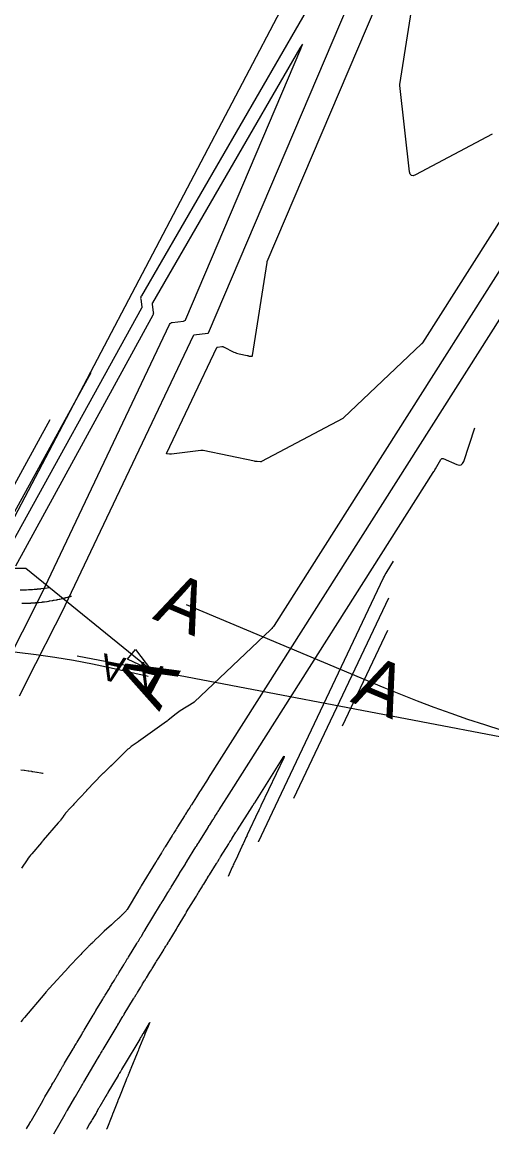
# Model space of a CAD drawing. Extents: x 688474 to 694748, y 765018 to 767373.
# Drawn here: x 688853.2 to 688960.5, y 766872 to 767124.6 of the extents above; entities that cross this region are included whole.
import ezdxf

# ---------------------------------------------------------------- set-up
doc = ezdxf.new("R2010")
doc.units = 0
for name, color, linetype in [('Default', 7, 'Continuous'), ('Prop_Contours_Major', 7, 'Continuous'), ('Prop_Contours_Minor', 7, 'Continuous'), ('R_Horz Alg', 7, 'Continuous')]:
    doc.layers.add(name, color=color, linetype=linetype)

msp = doc.modelspace()

# ---------------------------------------------------------------- linework, layer by layer
at = {"layer": 'Default'}
msp.add_lwpolyline([(689001.05, 766954.08), (688971.09, 766959.79), (688865.78, 766979.87)], dxfattribs=at)
at = {"layer": 'Prop_Contours_Major'}
for points in [[(688929.91, 767147.6), (688880.43, 767062.16), (688880.34, 767061.97), (688880.29, 767061.78), (688880.26, 767061.57), (688880.28, 767061.37), (688880.54, 767059.61), (688880.54, 767059.53), (688880.53, 767059.45), (688880.51, 767059.38), (688880.48, 767059.31), (688849.65, 767003.45)], [(688852.62, 766970.81), (688854.13, 766973.82), (688854.15, 766973.86), (688862.99, 766991.35), (688863, 766991.37), (688863.01, 766991.39), (688863.02, 766991.41), (688863.03, 766991.43), (688892.38, 767053.23), (688892.38, 767053.23), (688892.39, 767053.23), (688895.65, 767053.62), (688895.69, 767053.63), (688895.73, 767053.65), (688895.75, 767053.67), (688895.77, 767053.71), (688934.73, 767145.25)], [(688992.14, 767115.06), (688910.76, 766986.88), (688910.6, 766986.64), (688910.42, 766986.41), (688910.22, 766986.19), (688910.02, 766985.98), (688892.48, 766969.38), (688892.47, 766969.36), (688892.45, 766969.35), (688892.43, 766969.33), (688892.41, 766969.32), (688889.3, 766967.38), (688888.98, 766967.17), (688888.66, 766966.95), (688888.36, 766966.72), (688888.06, 766966.48), (688886.89, 766965.49), (688886.59, 766965.25), (688886.29, 766965.01), (688885.98, 766964.78), (688885.67, 766964.56), (688879.77, 766960.39), (688879.77, 766960.38), (688879.75, 766960.37), (688879.75, 766960.37), (688879.73, 766960.36), (688878.13, 766959.22), (688877.86, 766959.03), (688877.61, 766958.83), (688877.36, 766958.61), (688877.12, 766958.39), (688873.74, 766955.06), (688873.7, 766955.03), (688873.66, 766954.99), (688873.62, 766954.96), (688873.58, 766954.93), (688873.42, 766954.8), (688873.38, 766954.77), (688873.34, 766954.74), (688873.3, 766954.71), (688873.27, 766954.67), (688871.92, 766953.31), (688871.87, 766953.27), (688871.83, 766953.23), (688871.78, 766953.19), (688871.74, 766953.15), (688871.55, 766953), (688871.5, 766952.97), (688871.46, 766952.93), (688871.41, 766952.89), (688871.37, 766952.84), (688868.03, 766949.36), (688868.02, 766949.35), (688868.01, 766949.33), (688867.99, 766949.32), (688867.98, 766949.3), (688867.93, 766949.23), (688867.91, 766949.21), (688867.9, 766949.19), (688867.88, 766949.17), (688867.87, 766949.16), (688865.04, 766946.11), (688864.84, 766945.89), (688864.64, 766945.67), (688864.44, 766945.46), (688864.24, 766945.24), (688863.13, 766944.04), (688863.08, 766943.99), (688863.04, 766943.93), (688862.99, 766943.88), (688862.95, 766943.82), (688862.78, 766943.58), (688862.74, 766943.53), (688862.7, 766943.47), (688862.66, 766943.41), (688862.61, 766943.35), (688861.98, 766942.45), (688861.85, 766942.29), (688861.73, 766942.12), (688861.6, 766941.96), (688861.46, 766941.8), (688858.01, 766937.84), (688857.99, 766937.82), (688857.98, 766937.81), (688857.97, 766937.79), (688857.96, 766937.77), (688857.91, 766937.71), (688857.9, 766937.69), (688857.89, 766937.67), (688857.87, 766937.66), (688857.86, 766937.64), (688857.73, 766937.49), (688857.71, 766937.46), (688857.68, 766937.43), (688857.65, 766937.4), (688857.63, 766937.37), (688855.39, 766934.77), (688855.12, 766934.44), (688854.85, 766934.11), (688854.59, 766933.76), (688854.35, 766933.41), (688853.03, 766931.46)], [(688853.15, 766991.95), (688853.65, 766991.96), (688853.67, 766991.96), (688853.69, 766991.96), (688853.78, 766991.96), (688853.87, 766991.96), (688853.89, 766991.96), (688853.91, 766991.96), (688853.92, 766991.96), (688853.94, 766991.96), (688854.22, 766991.97), (688854.36, 766991.98), (688854.82, 766992), (688854.85, 766992), (688854.88, 766992), (688854.99, 766992), (688855.1, 766992.01), (688855.13, 766992.01), (688855.15, 766992.01), (688855.17, 766992.01), (688855.19, 766992.02), (688855.5, 766992.04), (688855.62, 766992.05), (688855.74, 766992.05), (688856.27, 766992.09), (688856.33, 766992.1), (688856.39, 766992.1), (688856.45, 766992.11), (688856.51, 766992.11), (688856.74, 766992.13), (688856.85, 766992.15), (688856.97, 766992.16), (688857.61, 766992.22), (688857.63, 766992.22), (688857.65, 766992.23), (688857.75, 766992.24), (688857.84, 766992.25), (688857.86, 766992.25), (688857.89, 766992.25), (688857.91, 766992.26), (688857.93, 766992.26), (688858.15, 766992.29), (688858.24, 766992.3), (688858.33, 766992.31), (688858.86, 766992.38), (688858.9, 766992.39), (688858.93, 766992.39), (688858.95, 766992.4), (688859.24, 766992.44), (688859.35, 766992.46), (688859.45, 766992.48), (688860.02, 766992.57), (688860.06, 766992.58), (688860.1, 766992.58), (688860.14, 766992.59), (688860.17, 766992.6), (688860.33, 766992.63), (688860.41, 766992.64), (688860.49, 766992.65), (688860.96, 766992.74), (688860.99, 766992.75), (688861.02, 766992.76), (688861.12, 766992.77), (688861.27, 766992.81), (688861.3, 766992.81), (688861.32, 766992.82), (688861.35, 766992.82), (688861.38, 766992.83), (688861.63, 766992.88), (688861.68, 766992.9), (688861.73, 766992.91), (688861.79, 766992.92), (688861.84, 766992.93), (688862.4, 766993.05), (688862.47, 766993.07), (688862.54, 766993.09), (688862.61, 766993.11), (688862.69, 766993.12), (688862.97, 766993.2), (688863.05, 766993.21), (688863.12, 766993.23), (688863.19, 766993.25), (688863.26, 766993.27), (688863.69, 766993.38), (688863.72, 766993.39), (688863.75, 766993.39), (688863.78, 766993.4), (688863.81, 766993.41), (688863.97, 766993.45), (688864.05, 766993.47), (688864.16, 766993.5), (688864.19, 766993.51), (688864.23, 766993.53), (688864.35, 766993.56), (688864.44, 766993.58)], [(688936.67, 766985.72), (688926.31, 766963.87)], [(688852.92, 766953.95), (688853.68, 766953.84), (688853.75, 766953.83), (688854.61, 766953.71), (688854.64, 766953.7), (688854.67, 766953.7), (688854.7, 766953.69), (688854.74, 766953.69), (688855.33, 766953.6), (688855.38, 766953.59), (688855.43, 766953.58), (688855.63, 766953.55), (688855.66, 766953.55), (688856.52, 766953.41), (688856.55, 766953.41), (688856.59, 766953.4), (688856.62, 766953.4), (688856.65, 766953.39), (688857.45, 766953.26), (688857.52, 766953.25), (688857.58, 766953.24), (688857.84, 766953.2), (688857.87, 766953.2), (688858.03, 766953.17)]]:
    msp.add_lwpolyline(points, dxfattribs=at)
at = {"layer": 'Prop_Contours_Minor'}
for points in [[(688960.55, 767099.05), (688943.08, 767089.77), (688942.54, 767089.58), (688942.13, 767089.63), (688941.86, 767089.94), (688941.71, 767090.49), (688939.45, 767110.19), (688939.44, 767110.24), (688939.44, 767110.29), (688939.44, 767110.33), (688939.45, 767110.38), (688943.17, 767134.12), (688943.23, 767134.44), (688943.31, 767134.76), (688943.41, 767135.08), (688943.53, 767135.39), (688945.06, 767138.97), (688945.35, 767139.67), (688945.65, 767140.36), (688945.95, 767141.06), (688946.26, 767141.76), (688985.58, 767232.35)], [(688986.13, 767116.74), (688944.65, 767051.41), (688944.6, 767051.35), (688944.55, 767051.28), (688944.5, 767051.22), (688944.44, 767051.16), (688926.64, 767034.3), (688926.6, 767034.27), (688926.56, 767034.24), (688926.52, 767034.21), (688926.47, 767034.18), (688907.87, 767024.3), (688907.81, 767024.28), (688907.75, 767024.26), (688907.69, 767024.25), (688907.63, 767024.25), (688906.86, 767024.3), (688906.71, 767024.31), (688906.56, 767024.33), (688906.41, 767024.35), (688906.26, 767024.38), (688894.56, 767026.81), (688894.43, 767026.84), (688894.3, 767026.85), (688894.17, 767026.85), (688894.04, 767026.84), (688887.3, 767025.99), (688887.18, 767025.98), (688887.06, 767025.98), (688886.94, 767025.98), (688886.83, 767025.99), (688886.35, 767026.04), (688886.25, 767026.06), (688886.2, 767026.11), (688886.19, 767026.18), (688886.22, 767026.27), (688897.64, 767050.34), (688897.67, 767050.38), (688897.71, 767050.42), (688897.76, 767050.44), (688897.81, 767050.46), (688898.8, 767050.57), (688898.91, 767050.58), (688899.01, 767050.57), (688899.11, 767050.54), (688899.21, 767050.5), (688901.53, 767049.32), (688901.83, 767049.18), (688902.13, 767049.07), (688902.45, 767048.97), (688902.77, 767048.9), (688904.63, 767048.56), (688904.67, 767048.55), (688904.71, 767048.54), (688904.75, 767048.52), (688904.79, 767048.51), (688904.94, 767048.43), (688904.97, 767048.42), (688905.01, 767048.41), (688905.05, 767048.4), (688905.09, 767048.39), (688905.59, 767048.36), (688905.67, 767048.37), (688905.74, 767048.4), (688905.79, 767048.46), (688905.81, 767048.54), (688909.14, 767069.78), (688909.15, 767069.83), (688909.16, 767069.89), (688909.18, 767069.94), (688909.2, 767069.99), (688940.22, 767142.88)], [(688848.84, 766976.65), (688857.69, 766994.16), (688857.7, 766994.18), (688857.71, 766994.2), (688886.89, 767055.63), (688887, 767055.81), (688887.14, 767055.94), (688887.31, 767056.03), (688887.5, 767056.08), (688890.02, 767056.37), (688890.21, 767056.42), (688890.37, 767056.5), (688890.49, 767056.63), (688890.59, 767056.8), (688916.88, 767118.58), (688917.2, 767119.35), (688917.26, 767119.63), (688917.07, 767119.41), (688916.64, 767118.7), (688882.98, 767060.57), (688882.93, 767060.48), (688882.91, 767060.39), (688882.9, 767060.29), (688882.9, 767060.19), (688883.16, 767058.43), (688883.17, 767058.25), (688883.16, 767058.06), (688883.11, 767057.89), (688883.03, 767057.72), (688851.68, 767000.41)], [(688981.42, 767087.02), (688895.7, 766952.01), (688895.68, 766951.97), (688893.94, 766949.23), (688893.71, 766948.87), (688893.49, 766948.51), (688893.26, 766948.15), (688893.03, 766947.79), (688891.88, 766945.96), (688891.77, 766945.8), (688891.67, 766945.64), (688891.57, 766945.48), (688891.47, 766945.32), (688890.98, 766944.55), (688890.93, 766944.46), (688890.87, 766944.36), (688890.81, 766944.27), (688890.75, 766944.18), (688890.52, 766943.81), (688890.46, 766943.72), (688890.41, 766943.63), (688890.35, 766943.54), (688890.29, 766943.44), (688888.7, 766940.89), (688888.6, 766940.73), (688888.49, 766940.56), (688888.39, 766940.4), (688888.29, 766940.24), (688887.88, 766939.58), (688887.78, 766939.42), (688887.68, 766939.26), (688887.58, 766939.09), (688887.47, 766938.93), (688885.88, 766936.35), (688885.81, 766936.24), (688885.74, 766936.13), (688885.67, 766936.01), (688885.6, 766935.9), (688885.33, 766935.46), (688885.26, 766935.35), (688885.19, 766935.24), (688885.12, 766935.12), (688885.05, 766935.01), (688884.03, 766933.36), (688883.97, 766933.25), (688883.9, 766933.15), (688883.78, 766932.95), (688883.75, 766932.89), (688883.71, 766932.84), (688883.68, 766932.79), (688883.65, 766932.74), (688880.4, 766927.42), (688880.33, 766927.3), (688880.25, 766927.17), (688880.08, 766926.9), (688880.05, 766926.85), (688880.02, 766926.8), (688880, 766926.76), (688879.97, 766926.71), (688879.8, 766926.43), (688879.78, 766926.4), (688877.16, 766922.06), (688877.06, 766921.9), (688876.95, 766921.75), (688876.82, 766921.61), (688876.69, 766921.47), (688875.99, 766920.78), (688875.93, 766920.72), (688875.87, 766920.66), (688875.81, 766920.6), (688875.75, 766920.54), (688875.44, 766920.24), (688875.42, 766920.21), (688875.39, 766920.19), (688875.37, 766920.16), (688875.35, 766920.14), (688875.25, 766920.05), (688875.22, 766920.02), (688875.2, 766920), (688875.17, 766919.98), (688875.15, 766919.95), (688874.23, 766919.12), (688874.07, 766918.97), (688873.91, 766918.82), (688873.75, 766918.68), (688873.58, 766918.53), (688871.93, 766917.06), (688871.67, 766916.83), (688871.43, 766916.6), (688871.18, 766916.36), (688870.94, 766916.13), (688869.76, 766914.94), (688869.63, 766914.81), (688869.5, 766914.69), (688869.38, 766914.56), (688869.25, 766914.44), (688868.72, 766913.96), (688868.59, 766913.84), (688868.46, 766913.71), (688868.34, 766913.59), (688868.21, 766913.46), (688866.85, 766912.05), (688866.59, 766911.78), (688866.34, 766911.52), (688866.08, 766911.25), (688865.82, 766910.98), (688864.36, 766909.46), (688864.31, 766909.42), (688864.27, 766909.37), (688864.23, 766909.32), (688864.18, 766909.28), (688864.01, 766909.09), (688863.96, 766909.05), (688863.92, 766909), (688863.88, 766908.95), (688863.83, 766908.91), (688859.34, 766903.99), (688859.33, 766903.98), (688859.32, 766903.98), (688859.32, 766903.97), (688859.31, 766903.96), (688859.29, 766903.93), (688859.28, 766903.92), (688859.27, 766903.91), (688859.27, 766903.9), (688859.26, 766903.9), (688858.64, 766903.19), (688858.63, 766903.18), (688858.63, 766903.18), (688858.6, 766903.15), (688858.46, 766902.96), (688858.44, 766902.93), (688858.42, 766902.89), (688858.39, 766902.86), (688858.36, 766902.83), (688853.72, 766897.38), (688853.63, 766897.28), (688853.54, 766897.17), (688853.45, 766897.07), (688853.36, 766896.96), (688852.88, 766896.39)], [(688847.99, 767006.65), (688868.96, 767044.65)], [(688846.56, 767010.26), (688859.59, 767033.88)], [(688854.2, 766871.96), (688854.23, 766872), (688854.28, 766872.09), (688854.87, 766873.13), (688854.91, 766873.19), (688854.94, 766873.25), (688854.98, 766873.32), (688855.01, 766873.38), (688855.16, 766873.63), (688855.23, 766873.76), (688855.31, 766873.89), (688857.9, 766878.38), (688857.94, 766878.45), (688857.98, 766878.53), (688858.02, 766878.6), (688858.06, 766878.67), (688858.23, 766878.95), (688858.31, 766879.09), (688858.39, 766879.24), (688859.79, 766881.64), (688859.84, 766881.73), (688859.9, 766881.82), (688859.95, 766881.91), (688860, 766882.01), (688860.21, 766882.37), (688860.27, 766882.46), (688860.32, 766882.55), (688860.37, 766882.64), (688860.42, 766882.73), (688861.56, 766884.67), (688861.67, 766884.86), (688861.78, 766885.05), (688861.89, 766885.24), (688862.01, 766885.43), (688862.45, 766886.19), (688862.57, 766886.38), (688862.68, 766886.57), (688862.79, 766886.76), (688862.9, 766886.95), (688864.85, 766890.25), (688864.88, 766890.3), (688864.91, 766890.36), (688864.94, 766890.41), (688864.97, 766890.46), (688865.12, 766890.72), (688865.19, 766890.82), (688865.22, 766890.88), (688865.5, 766891.35), (688865.56, 766891.45), (688865.61, 766891.55), (688865.67, 766891.64), (688865.73, 766891.74), (688866.8, 766893.53), (688867, 766893.87), (688867.2, 766894.2), (688867.4, 766894.53), (688867.6, 766894.86), (688869.42, 766897.92), (688869.45, 766897.97), (688869.48, 766898.02), (688869.51, 766898.07), (688869.54, 766898.12), (688869.69, 766898.36), (688869.75, 766898.46), (688869.78, 766898.51), (688869.91, 766898.74), (688869.94, 766898.79), (688869.98, 766898.84), (688870.01, 766898.9), (688870.04, 766898.95), (688871.41, 766901.22), (688871.61, 766901.54), (688871.81, 766901.87), (688872, 766902.19), (688872.2, 766902.52), (688873.12, 766904.04), (688873.25, 766904.25), (688873.38, 766904.47), (688873.51, 766904.68), (688873.64, 766904.9), (688874.26, 766905.92), (688874.35, 766906.06), (688874.43, 766906.19), (688874.52, 766906.33), (688874.6, 766906.47), (688874.93, 766907.02), (688875.02, 766907.15), (688875.1, 766907.29), (688875.19, 766907.43), (688875.27, 766907.57), (688876.41, 766909.43), (688876.5, 766909.57), (688876.59, 766909.72), (688876.68, 766909.87), (688876.77, 766910.01), (688877.13, 766910.6), (688877.22, 766910.75), (688877.31, 766910.89), (688877.4, 766911.04), (688877.49, 766911.19), (688879.41, 766914.28), (688879.49, 766914.42), (688879.58, 766914.56), (688879.67, 766914.7), (688879.76, 766914.85), (688880.11, 766915.41), (688880.19, 766915.56), (688880.28, 766915.7), (688880.37, 766915.84), (688880.46, 766915.98), (688881.03, 766916.91), (688881.1, 766917.03), (688881.22, 766917.22), (688881.24, 766917.26), (688881.27, 766917.3), (688881.29, 766917.34), (688881.31, 766917.37), (688884.83, 766923.2), (688884.9, 766923.31), (688884.96, 766923.41), (688885.09, 766923.63), (688885.12, 766923.68), (688885.15, 766923.73), (688885.18, 766923.78), (688885.21, 766923.82), (688885.38, 766924.11), (688885.39, 766924.13), (688886.51, 766925.95), (688886.7, 766926.26), (688886.88, 766926.56), (688887.07, 766926.87), (688887.25, 766927.17), (688889.05, 766930.1), (688889.07, 766930.14), (688889.09, 766930.17), (688889.16, 766930.28), (688889.17, 766930.3), (688890.48, 766932.43), (688890.51, 766932.47), (688890.54, 766932.52), (688890.56, 766932.57), (688890.59, 766932.61), (688890.74, 766932.84), (688890.79, 766932.94), (688890.82, 766932.98), (688892.91, 766936.36), (688892.97, 766936.44), (688893.02, 766936.52), (688893.07, 766936.6), (688893.12, 766936.69), (688893.33, 766937.02), (688893.38, 766937.1), (688893.43, 766937.18), (688893.48, 766937.26), (688893.53, 766937.35), (688895.67, 766940.77), (688895.7, 766940.82), (688895.74, 766940.87), (688895.77, 766940.93), (688895.8, 766940.98), (688895.93, 766941.19), (688896, 766941.29), (688896.06, 766941.4), (688896.75, 766942.49), (688896.88, 766942.69), (688897, 766942.88), (688897.12, 766943.07), (688897.24, 766943.27), (688897.73, 766944.04), (688897.86, 766944.24), (688897.98, 766944.43), (688898.1, 766944.62), (688898.23, 766944.82), (688900.99, 766949.18), (688901.01, 766949.22), (688947.12, 767021.84), (688947.24, 767022.04), (688947.37, 767022.23), (688947.48, 767022.43), (688947.6, 767022.63), (688948.86, 767024.81), (688948.96, 767024.94), (688949.09, 767025.01), (688949.23, 767025.03), (688949.39, 767024.98), (688952.51, 767023.66), (688953.04, 767023.52), (688953.47, 767023.59), (688953.81, 767023.87), (688954.06, 767024.36), (688956.63, 767032.05)], [(688907.18, 766937.5), (688907.22, 766937.58), (688907.25, 766937.64), (688910.36, 766944.26), (688910.38, 766944.3), (688935.76, 766997.77), (688935.94, 766998.14), (688936.13, 766998.5), (688936.33, 766998.85), (688936.55, 766999.2), (688938.04, 767001.55)], [(688859.39, 766995.51), (688858.45, 766995.36), (688858.42, 766995.35), (688858.38, 766995.35), (688858.37, 766995.34), (688858.15, 766995.31), (688858.05, 766995.3), (688857.5, 766995.23), (688857.47, 766995.23), (688857.45, 766995.22), (688857.36, 766995.21), (688857.27, 766995.2), (688857.26, 766995.2), (688857.24, 766995.2), (688857.22, 766995.2), (688857.21, 766995.2), (688856.84, 766995.16), (688856.77, 766995.15), (688856.71, 766995.15), (688856.64, 766995.14), (688856.57, 766995.13), (688856.25, 766995.1), (688856.17, 766995.09), (688856.09, 766995.09), (688856.02, 766995.08), (688855.94, 766995.07), (688855.56, 766995.05), (688855.5, 766995.04), (688855.44, 766995.04), (688855.38, 766995.04), (688855.32, 766995.03), (688854.99, 766995.01), (688854.97, 766995.01), (688854.95, 766995.01), (688854.93, 766995.01), (688854.9, 766995), (688854.77, 766995), (688854.7, 766994.99), (688854.67, 766994.99), (688854.65, 766994.99), (688854.17, 766994.97), (688854.1, 766994.97), (688854.02, 766994.97), (688853.84, 766994.96), (688853.82, 766994.96), (688853.8, 766994.96), (688853.78, 766994.96), (688853.76, 766994.96), (688853.64, 766994.96), (688853.59, 766994.96), (688853.57, 766994.96), (688853.35, 766994.95), (688853.28, 766994.95), (688853.2, 766994.95), (688852.72, 766994.95)], [(688936.89, 766993.16), (688915.18, 766947.42)], [(688860.45, 766870.86), (688863.02, 766875.31), (688863.1, 766875.46), (688863.19, 766875.6), (688863.36, 766875.9), (688863.4, 766875.98), (688863.44, 766876.05), (688863.49, 766876.12), (688863.53, 766876.2), (688865.24, 766879.13), (688865.28, 766879.21), (688865.34, 766879.31), (688865.37, 766879.35), (688865.38, 766879.37), (688866.84, 766881.88), (688866.97, 766882.1), (688867.22, 766882.53), (688867.24, 766882.56), (688867.28, 766882.62), (688870.33, 766887.8), (688870.36, 766887.84), (688870.44, 766887.98), (688870.92, 766888.79), (688870.99, 766888.9), (688871.05, 766889.01), (688871.12, 766889.12), (688871.18, 766889.23), (688871.44, 766889.67), (688871.51, 766889.78), (688871.58, 766889.89), (688871.64, 766890), (688871.71, 766890.11), (688874.88, 766895.41), (688874.9, 766895.46), (688874.93, 766895.5), (688875.02, 766895.65), (688875.05, 766895.7), (688875.3, 766896.12), (688875.35, 766896.2), (688875.4, 766896.28), (688875.45, 766896.36), (688875.49, 766896.44), (688876.07, 766897.39), (688876.19, 766897.58), (688876.3, 766897.76), (688876.41, 766897.95), (688876.52, 766898.13), (688878.64, 766901.63), (688878.72, 766901.75), (688878.79, 766901.88), (688878.86, 766902), (688878.94, 766902.12), (688879.24, 766902.61), (688879.31, 766902.73), (688879.38, 766902.85), (688879.46, 766902.97), (688879.53, 766903.1), (688880.29, 766904.33), (688880.4, 766904.51), (688880.51, 766904.69), (688880.61, 766904.87), (688880.72, 766905.04), (688881.16, 766905.75), (688881.27, 766905.93), (688881.38, 766906.11), (688881.49, 766906.29), (688881.6, 766906.46), (688882.37, 766907.73), (688882.54, 766908), (688882.71, 766908.27), (688882.87, 766908.54), (688883.04, 766908.81), (688883.73, 766909.93), (688883.9, 766910.21), (688884.07, 766910.48), (688884.25, 766910.76), (688884.42, 766911.03), (688885.54, 766912.85), (688885.6, 766912.95), (688885.67, 766913.06), (688885.73, 766913.16), (688885.79, 766913.26), (688886.05, 766913.68), (688886.11, 766913.78), (688886.17, 766913.87), (688886.23, 766913.97), (688886.29, 766914.07), (688886.53, 766914.45), (688886.59, 766914.55), (688886.65, 766914.65), (688886.71, 766914.75), (688886.77, 766914.84), (688888.42, 766917.58), (688888.63, 766917.93), (688888.84, 766918.27), (688889.05, 766918.62), (688889.26, 766918.97), (688890.48, 766920.99), (688890.5, 766921.02), (688890.52, 766921.05), (688890.54, 766921.08), (688890.56, 766921.11), (688890.67, 766921.29), (688890.73, 766921.41), (688890.76, 766921.44), (688890.78, 766921.48), (688892.85, 766924.87), (688893.01, 766925.12), (688893.17, 766925.38), (688893.32, 766925.63), (688893.48, 766925.89), (688894.16, 766927.01), (688894.29, 766927.22), (688894.42, 766927.43), (688894.55, 766927.64), (688894.68, 766927.85), (688895.35, 766928.93), (688895.4, 766929.02), (688895.45, 766929.1), (688895.51, 766929.19), (688895.56, 766929.28), (688895.78, 766929.63), (688895.83, 766929.71), (688895.88, 766929.8), (688895.94, 766929.89), (688895.99, 766929.98), (688897.57, 766932.53), (688897.65, 766932.65), (688897.73, 766932.78), (688897.81, 766932.9), (688897.89, 766933.03), (688898.2, 766933.53), (688898.28, 766933.66), (688898.36, 766933.79), (688898.43, 766933.91), (688898.51, 766934.04), (688900.38, 766937.02), (688900.45, 766937.13), (688900.52, 766937.24), (688900.58, 766937.35), (688900.65, 766937.46), (688900.93, 766937.9), (688901, 766938.01), (688901.07, 766938.12), (688901.13, 766938.23), (688901.2, 766938.34), (688902.05, 766939.68), (688902.1, 766939.77), (688902.16, 766939.86), (688902.27, 766940.03), (688902.3, 766940.07), (688902.32, 766940.12), (688902.35, 766940.16), (688902.38, 766940.2), (688905.74, 766945.5), (688905.79, 766945.59), (688905.85, 766945.68), (688905.91, 766945.77), (688905.96, 766945.86), (688906.3, 766946.39), (688906.32, 766946.43), (688912.86, 766956.73), (688913.01, 766956.96), (688913.08, 766957.02), (688913.05, 766956.93), (688912.94, 766956.68), (688907.72, 766945.69), (688907.7, 766945.65), (688907.36, 766944.91), (688907.24, 766944.66), (688907.12, 766944.41), (688904.62, 766939.1), (688904.59, 766939.03), (688904.56, 766938.96), (688904.52, 766938.89), (688904.49, 766938.82), (688904.33, 766938.46), (688904.23, 766938.25), (688903.75, 766937.22), (688903.66, 766937.02), (688903.57, 766936.83), (688903.47, 766936.63), (688903.38, 766936.43), (688902.59, 766934.73), (688902.36, 766934.22), (688902.13, 766933.72), (688901.66, 766932.71), (688901.55, 766932.46), (688901.43, 766932.21), (688901.32, 766931.96), (688901.2, 766931.71), (688900.23, 766929.59)], [(688872.55, 766871.92), (688872.57, 766871.96), (688872.59, 766872.01), (688873.75, 766874.96), (688873.83, 766875.14), (688873.9, 766875.33), (688873.92, 766875.37), (688873.93, 766875.42), (688873.95, 766875.46), (688873.97, 766875.51), (688875.04, 766878.2), (688875.14, 766878.46), (688875.24, 766878.71), (688875.27, 766878.77), (688875.3, 766878.84), (688875.32, 766878.9), (688875.35, 766878.96), (688876.97, 766882.99), (688877.15, 766883.44), (688877.47, 766884.25), (688877.52, 766884.36), (688877.56, 766884.47), (688877.61, 766884.58), (688877.65, 766884.7), (688877.94, 766885.41), (688878.04, 766885.64), (688878.06, 766885.69), (688878.08, 766885.74), (688878.09, 766885.78), (688878.11, 766885.83), (688879.55, 766889.34), (688879.68, 766889.67), (688879.82, 766890), (688879.95, 766890.32), (688880.09, 766890.65), (688880.86, 766892.55), (688880.88, 766892.59), (688880.89, 766892.63), (688880.91, 766892.66), (688880.93, 766892.7), (688881.05, 766893.01), (688881.2, 766893.36), (688881.23, 766893.43), (688881.26, 766893.5), (688881.29, 766893.58), (688881.32, 766893.65), (688881.7, 766894.58), (688881.89, 766895.03), (688882.3, 766896.02), (688882.37, 766896.19), (688882.38, 766896.25), (688882.34, 766896.2), (688882.24, 766896.06), (688880.83, 766893.72), (688880.8, 766893.67), (688880.38, 766892.98), (688880.35, 766892.94), (688880.33, 766892.89), (688880.3, 766892.85), (688880.27, 766892.8), (688880.14, 766892.58), (688880.08, 766892.49), (688880.06, 766892.44), (688876.51, 766886.52), (688876.49, 766886.48), (688876.46, 766886.43), (688876.39, 766886.3), (688876.36, 766886.26), (688875.93, 766885.53), (688875.86, 766885.41), (688875.79, 766885.3), (688875.72, 766885.18), (688875.65, 766885.06), (688875.38, 766884.6), (688875.31, 766884.48), (688875.24, 766884.36), (688875.17, 766884.25), (688875.1, 766884.13), (688872.8, 766880.24), (688872.74, 766880.14), (688872.68, 766880.04), (688872.62, 766879.94), (688872.56, 766879.83), (688872.32, 766879.43), (688872.26, 766879.32), (688872.2, 766879.22), (688872.14, 766879.12), (688872.09, 766879.02), (688870.96, 766877.1), (688870.89, 766876.97), (688870.81, 766876.84), (688870.74, 766876.72), (688870.66, 766876.59), (688870.37, 766876.09), (688870.3, 766875.96), (688870.22, 766875.83), (688870.15, 766875.71), (688870.08, 766875.58), (688869.2, 766874.07), (688869.05, 766873.82), (688868.91, 766873.57), (688868.77, 766873.33), (688868.62, 766873.08), (688868.05, 766872.09), (688867.91, 766871.84)]]:
    msp.add_lwpolyline(points, dxfattribs=at)
at = {"layer": 'R_Horz Alg'}
for p, q in [((688836.45, 766983.16), (689041.19, 767372.58)), ((688890.64, 766991.69), (688935.81, 766972.76)), ((688881.98, 766975.21), (688873.51, 766977.12))]:
    msp.add_line(p, q, dxfattribs=at)
msp.add_lwpolyline([(688882.72, 766976.64), (688854.02, 766999.89), (688848.02, 766999.89)], dxfattribs=at)
msp.add_lwpolyline([(688882.72, 766976.64), (688877.29, 766979.17), (688879.12, 766981.43)], close=True, dxfattribs=at)
for centre, radius, start, end in [((688829.43, 766782.04), 200, 77.2665, 116.9237), ((689046.52, 767236.98), 286.48, 247.2665, 273.4162)]:
    msp.add_arc(centre, radius, start, end, dxfattribs=at)

# ---------------------------------------------------------------- texts
for height, rotation, p in [(12, 337.2665, (688882.78, 766988.47)), (6, 167.2665, (688877.1, 766979.39)), (12, 62.2665, (688884.5, 766967.11)), (6, 167.2665, (688885.56, 766977.48)), (12, 337.2665, (688927.96, 766969.54))]:
    msp.add_text('A', height=height, rotation=rotation, dxfattribs=at).set_placement(p)

doc.saveas('drawing.dxf')
